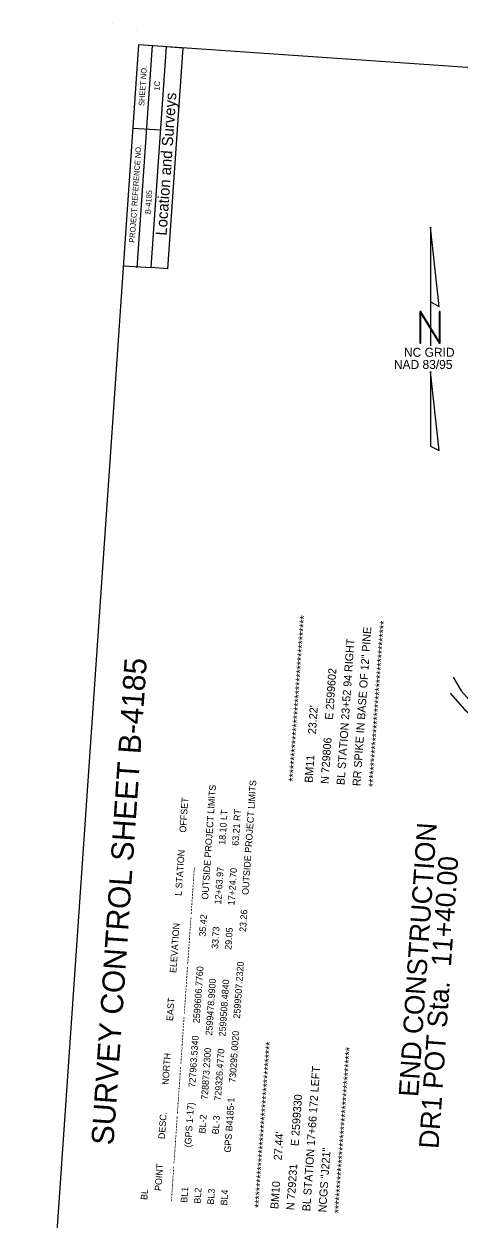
# Model space of a CAD drawing. Extents: x 2599057 to 2600057, y 728628 to 732947.
# Drawn here: x 2599057 to 2599397, y 732014 to 732947 of the extents above; entities that cross this region are included whole.
import ezdxf

# ---------------------------------------------------------------- set-up
doc = ezdxf.new("R2010")
doc.units = 0
for name, color, linetype in [('CTL North Arrow NAD 83 95 CELL', 7, 'Continuous'), ('CTL Sheet Border CELL', 7, 'Continuous'), ('CTL Sheet Text', 7, 'Continuous'), ('Old_Level_55', 7, 'Continuous'), ('Prop Horizontal Alignment Station Label', 7, 'Continuous')]:
    doc.layers.add(name, color=color, linetype=linetype)

# ---------------------------------------------------------------- blocks, each defined once
blk = doc.blocks.new('CTL NORTH ARROW NAD 83 95')
at = {"layer": 'CTL North Arrow NAD 83 95 CELL'}
for points in [[(-0.003, 1.746), (-0.003, 0.579), (0.135, 0.511)], [(-0.168, -0.065), (-0.154, -0.065), (-0.154, 0.401), (0.135, -0.065), (0.148, -0.065), (0.148, 0.428), (0.135, 0.428), (0.135, -0.038), (-0.154, 0.428), (-0.168, 0.428)], [(-0.003, -1.671), (0.135, -1.739), (-0.003, -0.505)]]:
    blk.add_lwpolyline(points, close=True, dxfattribs=at)
blk.add_lwpolyline([(-0.003, 0.579), (-0.003, -0.107)], dxfattribs=at)
for s, p in [('NC GRID', (-0.415, -0.277)), ('NAD 83/95', (-0.573, -0.467))]:
    blk.add_text(s, height=0.14, dxfattribs=at).set_placement(p)

msp = doc.modelspace()

# ---------------------------------------------------------------- linework, layer by layer
at = {"layer": 'CTL Sheet Border CELL'}
for p, q in [((2599125.56, 732947.44), (2599125.56, 732947.44)), ((2599144.76, 732942.19), (2599144.76, 732942.19)), ((2599144.76, 732942.19), (2599144.76, 732942.19)), ((2599145.17, 732756.89), (2599157.12, 732930.44)), ((2599141.79, 732866.13), (2599163.47, 732864.64)), ((2599134.38, 732758.62), (2599156.07, 732757.13))]:
    msp.add_line(p, q, dxfattribs=at)
for points in [[(2599146.23, 732931.19), (2599056.61, 731629.92), (2599967.49, 731567.19), (2600057.11, 732868.45)], [(2599156.07, 732757.13), (2599167.96, 732929.69), (2599180.72, 732928.81), (2599168.84, 732756.25)]]:
    msp.add_lwpolyline(points, close=True, dxfattribs=at)
at = {"layer": 'Old_Level_55'}
for points in [[(2599392.02, 732437.31), (2599398.33, 732426.52), (2599412.37, 732410.63), (2599427.82, 732398.95), (2599438.1, 732388.17), (2599445.41, 732378.83), (2599453.3, 732367.44), (2599461.18, 732357.95), (2599466.9, 732346.47), (2599478, 732334.86), (2599484.4, 732326.82), (2599488.48, 732326.29)], [(2599389.53, 732424.82), (2599401.21, 732411.85), (2599408.88, 732405.13), (2599423.25, 732392.7), (2599433.36, 732381.72), (2599440.68, 732373.69), (2599449.5, 732364.36), (2599455.83, 732356.26), (2599463.11, 732341.45), (2599469.26, 732327.75), (2599474.01, 732316.01), (2599471.41, 732311.09)]]:
    msp.add_lwpolyline(points, dxfattribs=at)

# ---------------------------------------------------------------- block references
at = {"layer": 'CTL North Arrow NAD 83 95 CELL', "xscale": 50, "yscale": 50}
msp.add_blockref('CTL NORTH ARROW NAD 83 95', (2599374.32, 732701.3), dxfattribs=at)

# ---------------------------------------------------------------- texts
at = {"layer": 'CTL Sheet Border CELL'}
for s, height, p in [('SHEET NO.', 4.348, (2599150.6, 732883.23)), ('1C', 4.348, (2599162.55, 732895.3)), ('Location and Surveys', 8.6958, (2599168.09, 732781.89)), ('PROJECT REFERENCE NO.', 4.3479, (2599143.15, 732776.4)), ('B-4185', 4.348, (2599155.56, 732798.8)), ('SURVEY CONTROL SHEET B-4185', 17.3913, (2599126.56, 732071.36))]:
    msp.add_text(s, height=height, rotation=86.0601, dxfattribs=at).set_placement(p)
at = {"layer": 'CTL Sheet Text'}
for s, height, p in [('****************************************', 6.25, (2599269.65, 732355.42)), ('****************************************', 6.25, (2599332, 732351.13)), ('BL STATION 23+52 94 RIGHT', 6.25, (2599307.06, 732352.84)), ('RR SPIKE IN BASE OF 12" PINE', 6.25, (2599319.53, 732351.99)), ('N 729806      E 2599602', 6.25, (2599294.59, 732353.7)), ("BM11       23.22'", 6.25, (2599282.12, 732354.56)), ('BL4               GPS B4185-1      730295.0020     2599507.2320            23.26      OUTSIDE PROJECT LIMITS                 ', 5.20833, (2599215.39, 732024.51)), ('BL1                (GPS 1-17)      727963.5340     2599606.7760            35.42      OUTSIDE PROJECT LIMITS                 ', 5.20833, (2599184.22, 732026.65)), ('    POINT          DESC.           NORTH             EAST          ELEVATION           L STATION       OFFSET', 5.20833, (2599163.43, 732028.09)), ('BL2                      BL-2      728873.2300     2599478.9900            33.73         12+63.97         18.10 LT', 5.20833, (2599194.61, 732025.94)), ('BL3                      BL-3      729326.4770     2599508.4840            29.05         17+24.70         63.21 RT', 5.20833, (2599205, 732025.22)), ('------------ ---------------- ---------------- ---------------- ---------------- ---------------- ----------------', 5.20833, (2599173.82, 732027.37)), ('****************************************', 6.25, (2599242.86, 732022.52)), ('****************************************', 6.25, (2599305.22, 732018.22)), ('BL STATION 17+66 172 LEFT', 6.25, (2599280.28, 732019.94)), ('N 729231      E 2599330', 6.25, (2599267.81, 732020.8)), ("BM10       27.44'", 6.25, (2599255.34, 732021.66)), ('NCGS "J221"', 6.25, (2599292.75, 732019.08)), ('BL', 5.208, (2599153.04, 732028.8))]:
    msp.add_text(s, height=height, rotation=86.0601, dxfattribs=at).set_placement(p)
at = {"layer": 'Prop Horizontal Alignment Station Label'}
for s, p in [('END CONSTRUCTION', (2599364.68, 732109.11)), ('   DR1 POT Sta.  11+40.00', (2599379.36, 732051.52))]:
    msp.add_text(s, height=15.3562, rotation=86.10149, dxfattribs=at).set_placement(p)

doc.saveas('drawing.dxf')
